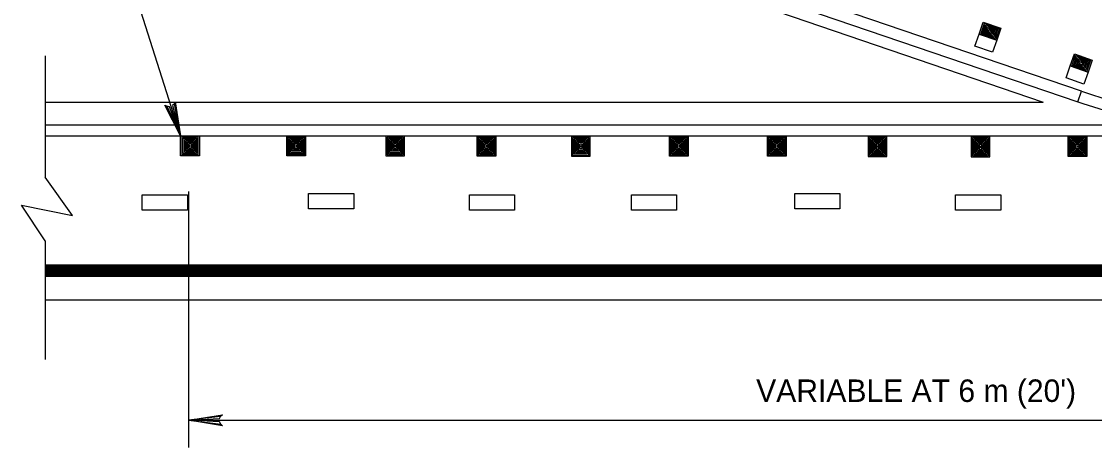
# Model space of a CAD drawing. Extents: x 639362 to 641108, y 298458 to 299646.
# Drawn here: x 639509.1 to 639652.3, y 299494 to 299550.9 of the extents above; entities that cross this region are included whole.
import ezdxf

# ---------------------------------------------------------------- set-up
doc = ezdxf.new("R2010")
doc.units = 0
doc.layers.add('2', color=7, linetype='Continuous')

msp = doc.modelspace()

# ---------------------------------------------------------------- linework, layer by layer
at = {"layer": '2'}
for p, q in [((639530.34, 299535.6), (639521.36, 299563.76)), ((639650.51, 299541.55), (639602.91, 299557.79)), ((639602.39, 299556.38), (639650.01, 299540.13)), ((639601.94, 299554.95), (639645.41, 299540.11)), ((639636.86, 299549.17), (639637.42, 299550.77)), ((639637.07, 299549.18), (639637.57, 299550.63)), ((639637.27, 299549.23), (639637.7, 299550.47)), ((639637.42, 299550.77), (639639.78, 299549.95)), ((639637.57, 299550.63), (639639.58, 299549.93)), ((639637.7, 299550.47), (639639.38, 299549.88)), ((639639.22, 299548.35), (639636.86, 299549.17)), ((639639.08, 299548.49), (639637.07, 299549.18)), ((639638.95, 299548.65), (639637.27, 299549.23)), ((639637.48, 299549.28), (639637.83, 299550.3)), ((639638.82, 299548.82), (639637.48, 299549.28)), ((639637.68, 299549.33), (639637.96, 299550.13)), ((639638.69, 299548.98), (639637.68, 299549.33)), ((639637.83, 299550.3), (639639.17, 299549.83)), ((639637.89, 299549.38), (639638.09, 299549.97)), ((639638.56, 299549.15), (639637.89, 299549.38)), ((639637.96, 299550.13), (639638.97, 299549.79)), ((639638.09, 299549.97), (639638.76, 299549.74)), ((639638.09, 299549.43), (639638.22, 299549.8)), ((639638.43, 299549.31), (639638.09, 299549.43)), ((639638.22, 299549.8), (639638.56, 299549.69)), ((639638.35, 299549.64), (639638.29, 299549.48)), ((639638.56, 299549.69), (639638.43, 299549.31)), ((639638.76, 299549.74), (639638.56, 299549.15)), ((639638.97, 299549.79), (639638.69, 299548.98)), ((639639.17, 299549.83), (639638.82, 299548.82)), ((639639.38, 299549.88), (639638.95, 299548.65)), ((639639.58, 299549.93), (639639.08, 299548.49)), ((639639.78, 299549.95), (639639.22, 299548.35)), ((639512.29, 299546.29), (639512.29, 299530.08)), ((639649.03, 299544.92), (639649.59, 299546.53)), ((639649.23, 299544.94), (639649.73, 299546.39)), ((639649.44, 299544.99), (639649.86, 299546.22)), ((639649.59, 299546.53), (639651.95, 299545.71)), ((639649.64, 299545.04), (639649.99, 299546.06)), ((639649.73, 299546.39), (639651.74, 299545.69)), ((639649.86, 299546.22), (639651.54, 299545.64)), ((639649.99, 299546.06), (639651.34, 299545.59)), ((639651.39, 299544.11), (639649.03, 299544.92)), ((639651.24, 299544.24), (639649.23, 299544.94)), ((639651.11, 299544.41), (639649.44, 299544.99)), ((639650.98, 299544.57), (639649.64, 299545.04)), ((639649.85, 299545.09), (639650.13, 299545.89)), ((639650.85, 299544.74), (639649.85, 299545.09)), ((639650.05, 299545.14), (639650.26, 299545.73)), ((639650.72, 299544.9), (639650.05, 299545.14)), ((639650.13, 299545.89), (639651.13, 299545.54)), ((639650.26, 299545.73), (639650.93, 299545.49)), ((639650.26, 299545.18), (639650.39, 299545.56)), ((639650.59, 299545.07), (639650.26, 299545.18)), ((639650.39, 299545.56), (639650.72, 299545.44)), ((639650.52, 299545.4), (639650.46, 299545.23)), ((639650.72, 299545.44), (639650.59, 299545.07)), ((639650.93, 299545.49), (639650.72, 299544.9)), ((639651.13, 299545.54), (639650.85, 299544.74)), ((639651.34, 299545.59), (639650.98, 299544.57)), ((639651.54, 299545.64), (639651.11, 299544.41)), ((639651.74, 299545.69), (639651.24, 299544.24)), ((639651.95, 299545.71), (639651.39, 299544.11)), ((639650.01, 299540.13), (639650.51, 299541.55)), ((639512.29, 299540.11), (639645.41, 299540.11)), ((639512.29, 299537.09), (639661.38, 299537.09)), ((639512.29, 299535.59), (639737.89, 299535.59)), ((639530.34, 299535.6), (639532.84, 299535.6)), ((639530.34, 299532.95), (639530.34, 299535.6)), ((639530.53, 299535.47), (639532.65, 299535.47)), ((639530.53, 299533.08), (639530.53, 299535.47)), ((639530.7, 299535.29), (639532.48, 299535.29)), ((639530.7, 299533.25), (639530.7, 299535.29)), ((639530.88, 299535.11), (639532.3, 299535.11)), ((639530.88, 299533.43), (639530.88, 299535.11)), ((639531.06, 299534.94), (639532.12, 299534.94)), ((639531.06, 299533.61), (639531.06, 299534.94)), ((639531.24, 299533.79), (639531.24, 299534.76)), ((639531.24, 299534.76), (639531.95, 299534.76)), ((639531.95, 299534.76), (639531.95, 299533.79)), ((639532.12, 299534.94), (639532.12, 299533.61)), ((639532.3, 299535.11), (639532.3, 299533.43)), ((639532.48, 299535.29), (639532.48, 299533.25)), ((639532.65, 299535.47), (639532.65, 299533.08)), ((639532.84, 299535.6), (639532.84, 299532.95)), ((639544.52, 299535.57), (639547.01, 299535.57)), ((639544.52, 299532.92), (639544.52, 299535.57)), ((639544.7, 299535.44), (639546.83, 299535.44)), ((639544.7, 299533.05), (639544.7, 299535.44)), ((639544.88, 299535.26), (639546.66, 299535.26)), ((639544.88, 299533.22), (639544.88, 299535.26)), ((639545.06, 299535.08), (639546.48, 299535.08)), ((639545.06, 299533.4), (639545.06, 299535.08)), ((639545.24, 299534.91), (639546.3, 299534.91)), ((639545.24, 299533.58), (639545.24, 299534.91)), ((639545.41, 299533.76), (639545.41, 299534.73)), ((639545.41, 299534.73), (639546.12, 299534.73)), ((639546.12, 299534.73), (639546.12, 299533.76)), ((639546.3, 299534.91), (639546.3, 299533.58)), ((639546.48, 299535.08), (639546.48, 299533.4)), ((639546.66, 299535.26), (639546.66, 299533.22)), ((639546.83, 299535.44), (639546.83, 299533.05)), ((639547.01, 299535.57), (639547.01, 299532.92)), ((639560.21, 299535.57), (639557.71, 299535.57)), ((639557.71, 299535.57), (639557.71, 299532.92)), ((639560.02, 299535.44), (639557.89, 299535.44)), ((639557.89, 299535.44), (639557.89, 299533.05)), ((639559.84, 299535.26), (639558.07, 299535.26)), ((639558.07, 299535.26), (639558.07, 299533.22)), ((639559.67, 299535.08), (639558.25, 299535.08)), ((639558.25, 299535.08), (639558.25, 299533.4)), ((639559.49, 299534.91), (639558.43, 299534.91)), ((639558.43, 299534.91), (639558.43, 299533.58)), ((639558.6, 299534.73), (639558.6, 299533.76)), ((639559.31, 299534.73), (639558.6, 299534.73)), ((639559.31, 299533.76), (639559.31, 299534.73)), ((639559.49, 299533.58), (639559.49, 299534.91)), ((639559.67, 299533.4), (639559.67, 299535.08)), ((639559.84, 299533.22), (639559.84, 299535.26)), ((639560.02, 299533.05), (639560.02, 299535.44)), ((639560.21, 299532.92), (639560.21, 299535.57)), ((639569.89, 299535.54), (639572.39, 299535.54)), ((639569.89, 299532.89), (639569.89, 299535.54)), ((639570.07, 299535.41), (639572.2, 299535.41)), ((639570.07, 299533.01), (639570.07, 299535.41)), ((639570.25, 299535.23), (639572.03, 299535.23)), ((639570.25, 299533.19), (639570.25, 299535.23)), ((639570.43, 299535.05), (639571.85, 299535.05)), ((639570.43, 299533.37), (639570.43, 299535.05)), ((639570.61, 299534.87), (639571.67, 299534.87)), ((639570.61, 299533.55), (639570.61, 299534.87)), ((639570.79, 299533.72), (639570.79, 299534.7)), ((639570.79, 299534.7), (639571.49, 299534.7)), ((639571.49, 299534.7), (639571.49, 299533.72)), ((639571.67, 299534.87), (639571.67, 299533.55)), ((639571.85, 299535.05), (639571.85, 299533.37)), ((639572.03, 299535.23), (639572.03, 299533.19)), ((639572.2, 299535.41), (639572.2, 299533.01)), ((639572.39, 299535.54), (639572.39, 299532.89)), ((639584.98, 299535.53), (639582.48, 299535.53)), ((639582.48, 299535.53), (639582.48, 299532.88)), ((639584.8, 299535.4), (639582.67, 299535.4)), ((639582.67, 299535.4), (639582.67, 299533)), ((639584.62, 299535.22), (639582.84, 299535.22)), ((639582.84, 299535.22), (639582.84, 299533.18)), ((639584.44, 299535.04), (639583.02, 299535.04)), ((639583.02, 299535.04), (639583.02, 299533.36)), ((639584.26, 299534.86), (639583.2, 299534.86)), ((639583.2, 299534.86), (639583.2, 299533.54)), ((639583.38, 299534.69), (639583.38, 299533.71)), ((639584.09, 299534.69), (639583.38, 299534.69)), ((639584.09, 299533.71), (639584.09, 299534.69)), ((639584.26, 299533.54), (639584.26, 299534.86)), ((639584.44, 299533.36), (639584.44, 299535.04)), ((639584.62, 299533.18), (639584.62, 299535.22)), ((639584.8, 299533), (639584.8, 299535.4)), ((639584.98, 299532.88), (639584.98, 299535.53)), ((639595.54, 299535.55), (639598.03, 299535.55)), ((639595.54, 299532.89), (639595.54, 299535.55)), ((639595.72, 299535.41), (639597.85, 299535.41)), ((639595.72, 299533.02), (639595.72, 299535.41)), ((639595.9, 299535.24), (639597.68, 299535.24)), ((639595.9, 299533.2), (639595.9, 299535.24)), ((639596.08, 299535.06), (639597.5, 299535.06)), ((639596.08, 299533.38), (639596.08, 299535.06)), ((639596.26, 299534.88), (639597.32, 299534.88)), ((639596.26, 299533.55), (639596.26, 299534.88)), ((639596.44, 299533.73), (639596.44, 299534.71)), ((639596.44, 299534.71), (639597.14, 299534.71)), ((639597.14, 299534.71), (639597.14, 299533.73)), ((639597.32, 299534.88), (639597.32, 299533.55)), ((639597.5, 299535.06), (639597.5, 299533.38)), ((639597.68, 299535.24), (639597.68, 299533.2)), ((639597.85, 299535.41), (639597.85, 299533.02)), ((639598.03, 299535.55), (639598.03, 299532.89)), ((639608.63, 299535.53), (639611.13, 299535.53)), ((639608.63, 299532.88), (639608.63, 299535.53)), ((639608.82, 299535.4), (639610.95, 299535.4)), ((639608.82, 299533.01), (639608.82, 299535.4)), ((639609, 299535.22), (639610.77, 299535.22)), ((639609, 299533.19), (639609, 299535.22)), ((639609.17, 299535.05), (639610.59, 299535.05)), ((639609.17, 299533.36), (639609.17, 299535.05)), ((639609.35, 299534.87), (639610.42, 299534.87)), ((639609.35, 299533.54), (639609.35, 299534.87)), ((639609.53, 299533.72), (639609.53, 299534.69)), ((639609.53, 299534.69), (639610.24, 299534.69)), ((639610.24, 299534.69), (639610.24, 299533.72)), ((639610.42, 299534.87), (639610.42, 299533.54)), ((639610.59, 299535.05), (639610.59, 299533.36)), ((639610.77, 299535.22), (639610.77, 299533.19)), ((639610.95, 299535.4), (639610.95, 299533.01)), ((639611.13, 299535.53), (639611.13, 299532.88)), ((639624.55, 299535.5), (639622.05, 299535.5)), ((639622.05, 299535.5), (639622.05, 299532.84)), ((639624.36, 299535.36), (639622.23, 299535.36)), ((639622.23, 299535.36), (639622.23, 299532.97)), ((639624.18, 299535.19), (639622.41, 299535.19)), ((639622.41, 299535.19), (639622.41, 299533.15)), ((639624.01, 299535.01), (639622.59, 299535.01)), ((639622.59, 299535.01), (639622.59, 299533.32)), ((639623.83, 299534.83), (639622.76, 299534.83)), ((639622.76, 299534.83), (639622.76, 299533.5)), ((639622.94, 299534.65), (639622.94, 299533.68)), ((639623.65, 299534.65), (639622.94, 299534.65)), ((639623.65, 299533.68), (639623.65, 299534.65)), ((639623.83, 299533.5), (639623.83, 299534.83)), ((639624.01, 299533.32), (639624.01, 299535.01)), ((639624.18, 299533.15), (639624.18, 299535.19)), ((639624.36, 299532.97), (639624.36, 299535.36)), ((639624.55, 299532.84), (639624.55, 299535.5)), ((639638.31, 299535.45), (639635.82, 299535.45)), ((639635.82, 299535.45), (639635.82, 299532.8)), ((639638.13, 299535.32), (639636, 299535.32)), ((639636, 299535.32), (639636, 299532.93)), ((639637.95, 299535.14), (639636.17, 299535.14)), ((639636.17, 299535.14), (639636.17, 299533.11)), ((639637.77, 299534.97), (639636.35, 299534.97)), ((639636.35, 299534.97), (639636.35, 299533.28)), ((639637.6, 299534.79), (639636.53, 299534.79)), ((639636.53, 299534.79), (639636.53, 299533.46)), ((639636.71, 299534.61), (639636.71, 299533.64)), ((639637.42, 299534.61), (639636.71, 299534.61)), ((639637.42, 299533.64), (639637.42, 299534.61)), ((639637.6, 299533.46), (639637.6, 299534.79)), ((639637.77, 299533.28), (639637.77, 299534.97)), ((639637.95, 299533.11), (639637.95, 299535.14)), ((639638.13, 299532.93), (639638.13, 299535.32)), ((639638.31, 299532.8), (639638.31, 299535.45)), ((639648.74, 299535.51), (639651.24, 299535.51)), ((639648.74, 299532.85), (639648.74, 299535.51)), ((639648.93, 299535.37), (639651.06, 299535.37)), ((639648.93, 299532.98), (639648.93, 299535.37)), ((639649.11, 299535.2), (639650.88, 299535.2)), ((639649.11, 299533.16), (639649.11, 299535.2)), ((639649.28, 299535.02), (639650.7, 299535.02)), ((639649.28, 299533.34), (639649.28, 299535.02)), ((639649.46, 299534.84), (639650.53, 299534.84)), ((639649.46, 299533.51), (639649.46, 299534.84)), ((639649.64, 299533.69), (639649.64, 299534.67)), ((639649.64, 299534.67), (639650.35, 299534.67)), ((639650.35, 299534.67), (639650.35, 299533.69)), ((639650.53, 299534.84), (639650.53, 299533.51)), ((639650.7, 299535.02), (639650.7, 299533.34)), ((639650.88, 299535.2), (639650.88, 299533.16)), ((639651.06, 299535.37), (639651.06, 299532.98)), ((639651.24, 299535.51), (639651.24, 299532.85)), ((639532.48, 299533.25), (639530.7, 299533.25)), ((639532.3, 299533.43), (639530.88, 299533.43)), ((639532.12, 299533.61), (639531.06, 299533.61)), ((639531.95, 299533.79), (639531.24, 299533.79)), ((639531.42, 299534.58), (639531.77, 299534.58)), ((639531.42, 299533.96), (639531.42, 299534.58)), ((639531.77, 299533.96), (639531.42, 299533.96)), ((639531.59, 299534.41), (639531.59, 299534.14)), ((639531.77, 299534.58), (639531.77, 299533.96)), ((639546.66, 299533.22), (639544.88, 299533.22)), ((639546.48, 299533.4), (639545.06, 299533.4)), ((639546.3, 299533.58), (639545.24, 299533.58)), ((639546.12, 299533.76), (639545.41, 299533.76)), ((639545.59, 299534.56), (639545.94, 299534.56)), ((639545.59, 299533.93), (639545.59, 299534.56)), ((639545.94, 299533.93), (639545.59, 299533.93)), ((639545.76, 299534.38), (639545.76, 299534.11)), ((639545.94, 299534.56), (639545.94, 299533.93)), ((639558.07, 299533.22), (639559.84, 299533.22)), ((639558.25, 299533.4), (639559.67, 299533.4)), ((639558.43, 299533.58), (639559.49, 299533.58)), ((639558.6, 299533.76), (639559.31, 299533.76)), ((639559.13, 299534.56), (639558.78, 299534.56)), ((639558.78, 299534.56), (639558.78, 299533.93)), ((639558.78, 299533.93), (639559.13, 299533.93)), ((639558.96, 299534.38), (639558.96, 299534.11)), ((639559.13, 299533.93), (639559.13, 299534.56)), ((639572.03, 299533.19), (639570.25, 299533.19)), ((639571.85, 299533.37), (639570.43, 299533.37)), ((639571.67, 299533.55), (639570.61, 299533.55)), ((639571.49, 299533.72), (639570.79, 299533.72)), ((639570.96, 299534.52), (639571.32, 299534.52)), ((639570.96, 299533.9), (639570.96, 299534.52)), ((639571.32, 299533.9), (639570.96, 299533.9)), ((639571.14, 299534.34), (639571.14, 299534.08)), ((639571.32, 299534.52), (639571.32, 299533.9)), ((639582.84, 299533.18), (639584.62, 299533.18)), ((639583.02, 299533.36), (639584.44, 299533.36)), ((639583.2, 299533.54), (639584.26, 299533.54)), ((639583.38, 299533.71), (639584.09, 299533.71)), ((639583.91, 299534.51), (639583.55, 299534.51)), ((639583.55, 299534.51), (639583.55, 299533.89)), ((639583.55, 299533.89), (639583.91, 299533.89)), ((639583.73, 299534.33), (639583.73, 299534.07)), ((639583.91, 299533.89), (639583.91, 299534.51)), ((639597.68, 299533.2), (639595.9, 299533.2)), ((639597.5, 299533.38), (639596.08, 299533.38)), ((639597.32, 299533.55), (639596.26, 299533.55)), ((639597.14, 299533.73), (639596.44, 299533.73)), ((639596.61, 299534.53), (639596.97, 299534.53)), ((639596.61, 299533.91), (639596.61, 299534.53)), ((639596.97, 299533.91), (639596.61, 299533.91)), ((639596.79, 299534.35), (639596.79, 299534.08)), ((639596.97, 299534.53), (639596.97, 299533.91)), ((639610.77, 299533.19), (639609, 299533.19)), ((639610.59, 299533.36), (639609.17, 299533.36)), ((639610.42, 299533.54), (639609.35, 299533.54)), ((639610.24, 299533.72), (639609.53, 299533.72)), ((639609.71, 299534.52), (639610.06, 299534.52)), ((639609.71, 299533.89), (639609.71, 299534.52)), ((639610.06, 299533.89), (639609.71, 299533.89)), ((639609.88, 299534.34), (639609.88, 299534.07)), ((639610.06, 299534.52), (639610.06, 299533.89)), ((639622.59, 299533.32), (639624.01, 299533.32)), ((639622.76, 299533.5), (639623.83, 299533.5)), ((639622.94, 299533.68), (639623.65, 299533.68)), ((639623.47, 299534.48), (639623.12, 299534.48)), ((639623.12, 299534.48), (639623.12, 299533.86)), ((639623.12, 299533.86), (639623.47, 299533.86)), ((639623.3, 299534.3), (639623.3, 299534.03)), ((639623.47, 299533.86), (639623.47, 299534.48)), ((639636.35, 299533.28), (639637.77, 299533.28)), ((639636.53, 299533.46), (639637.6, 299533.46)), ((639636.71, 299533.64), (639637.42, 299533.64)), ((639637.24, 299534.44), (639636.89, 299534.44)), ((639636.89, 299534.44), (639636.89, 299533.81)), ((639636.89, 299533.81), (639637.24, 299533.81)), ((639637.06, 299534.26), (639637.06, 299533.99)), ((639637.24, 299533.81), (639637.24, 299534.44)), ((639650.88, 299533.16), (639649.11, 299533.16)), ((639650.7, 299533.34), (639649.28, 299533.34)), ((639650.53, 299533.51), (639649.46, 299533.51)), ((639650.35, 299533.69), (639649.64, 299533.69)), ((639649.82, 299534.49), (639650.17, 299534.49)), ((639649.82, 299533.87), (639649.82, 299534.49)), ((639650.17, 299533.87), (639649.82, 299533.87)), ((639649.99, 299534.31), (639649.99, 299534.04)), ((639650.17, 299534.49), (639650.17, 299533.87)), ((639532.84, 299532.95), (639530.34, 299532.95)), ((639532.65, 299533.08), (639530.53, 299533.08)), ((639547.01, 299532.92), (639544.52, 299532.92)), ((639546.83, 299533.05), (639544.7, 299533.05)), ((639557.71, 299532.92), (639560.21, 299532.92)), ((639557.89, 299533.05), (639560.02, 299533.05)), ((639572.39, 299532.89), (639569.89, 299532.89)), ((639572.2, 299533.01), (639570.07, 299533.01)), ((639582.48, 299532.88), (639584.98, 299532.88)), ((639582.67, 299533), (639584.8, 299533)), ((639598.03, 299532.89), (639595.54, 299532.89)), ((639597.85, 299533.02), (639595.72, 299533.02)), ((639611.13, 299532.88), (639608.63, 299532.88)), ((639610.95, 299533.01), (639608.82, 299533.01)), ((639622.05, 299532.84), (639624.55, 299532.84)), ((639622.23, 299532.97), (639624.36, 299532.97)), ((639622.41, 299533.15), (639624.18, 299533.15)), ((639635.82, 299532.8), (639638.31, 299532.8)), ((639636, 299532.93), (639638.13, 299532.93)), ((639636.17, 299533.11), (639637.95, 299533.11)), ((639651.24, 299532.85), (639648.74, 299532.85)), ((639651.06, 299532.98), (639648.93, 299532.98)), ((639515.93, 299524.97), (639512.29, 299530.08)), ((639525.22, 299525.67), (639525.22, 299527.74)), ((639525.22, 299527.74), (639531.24, 299527.74)), ((639531.24, 299527.74), (639531.24, 299525.67)), ((639531.37, 299528.16), (639531.37, 299494.02)), ((639547.41, 299525.86), (639547.41, 299527.93)), ((639547.41, 299527.93), (639553.43, 299527.93)), ((639553.43, 299527.93), (639553.43, 299525.86)), ((639568.86, 299525.67), (639568.86, 299527.74)), ((639568.86, 299527.74), (639574.87, 299527.74)), ((639574.87, 299527.74), (639574.87, 299525.67)), ((639590.49, 299525.67), (639590.49, 299527.74)), ((639590.49, 299527.74), (639596.5, 299527.74)), ((639596.5, 299527.74), (639596.5, 299525.67)), ((639612.27, 299525.86), (639612.27, 299527.93)), ((639612.27, 299527.93), (639618.29, 299527.93)), ((639618.29, 299527.93), (639618.29, 299525.86)), ((639633.73, 299525.67), (639633.73, 299527.74)), ((639633.73, 299527.74), (639639.74, 299527.74)), ((639639.74, 299527.74), (639639.74, 299525.67)), ((639512.29, 299521.6), (639509.11, 299526.37)), ((639509.11, 299526.37), (639515.93, 299524.97)), ((639531.24, 299525.67), (639525.22, 299525.67)), ((639553.43, 299525.86), (639547.41, 299525.86)), ((639574.87, 299525.67), (639568.86, 299525.67)), ((639596.5, 299525.67), (639590.49, 299525.67)), ((639618.29, 299525.86), (639612.27, 299525.86)), ((639639.74, 299525.67), (639633.73, 299525.67)), ((639512.29, 299521.6), (639512.29, 299505.78)), ((639512.29, 299518.38), (639813.29, 299518.38)), ((639512.29, 299518.23), (639813.29, 299518.23)), ((639512.29, 299518.08), (639813.29, 299518.08)), ((639512.29, 299517.93), (639813.29, 299517.93)), ((639512.29, 299517.78), (639813.29, 299517.78)), ((639512.29, 299517.63), (639813.29, 299517.63)), ((639512.29, 299517.48), (639813.29, 299517.48)), ((639512.29, 299517.33), (639813.29, 299517.33)), ((639512.29, 299517.18), (639813.29, 299517.18)), ((639512.29, 299517.03), (639813.29, 299517.03)), ((639512.29, 299516.88), (639813.29, 299516.88)), ((639512.29, 299513.74), (639813.29, 299513.74)), ((639531.37, 299497.67), (639734.72, 299497.67))]:
    msp.add_line(p, q, dxfattribs=at)
for points in [[(639636.86, 299549.17), (639639.22, 299548.35), (639638.67, 299546.75), (639636.31, 299547.56)], [(639649.03, 299544.92), (639651.39, 299544.11), (639650.83, 299542.5), (639648.47, 299543.32)]]:
    msp.add_lwpolyline(points, close=True, dxfattribs=at)
for points in [[(639529.52, 299539.88), (639529.27, 299539.63), (639530.34, 299535.6), (639529.52, 299539.88), (639529.63, 299540.14), (639530.34, 299535.6), (639528.86, 299539.48), (639528.52, 299539.54), (639530.34, 299535.6), (639528.25, 299539.69), (639528.52, 299539.54)], [(639535.69, 299497.12), (639535.53, 299497.44), (639531.37, 299497.67), (639535.69, 299497.12), (639535.91, 299496.93), (639531.37, 299497.67), (639535.52, 299497.87), (639535.67, 299498.18), (639531.37, 299497.67), (639535.91, 299498.39), (639535.67, 299498.18)]]:
    msp.add_lwpolyline(points, dxfattribs=at)
for centre, radius, start, end in [((639679.6, 299628.88), 92.05, 251.5767, 265.7693), ((639680.87, 299632.65), 97.53, 251.5563, 258.4732)]:
    msp.add_arc(centre, radius, start, end, dxfattribs=at)

# ---------------------------------------------------------------- texts
msp.add_text("VARIABLE AT 6 m (20')", height=3, dxfattribs=at).set_placement((639607.12, 299500.1))

doc.saveas('drawing.dxf')
